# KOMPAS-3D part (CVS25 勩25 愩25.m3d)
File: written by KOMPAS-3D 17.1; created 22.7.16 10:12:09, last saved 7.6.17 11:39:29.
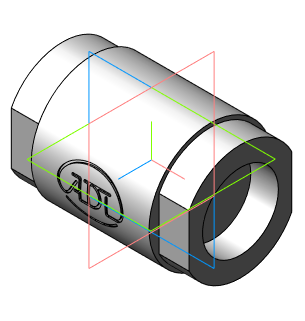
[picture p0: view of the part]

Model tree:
1. Операция без истории:2  (labels: Сталь 20  ГОСТ 1050-88)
